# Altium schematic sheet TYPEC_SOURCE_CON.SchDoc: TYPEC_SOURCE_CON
size A4; SheetNumber: 5; SheetTotal: 10
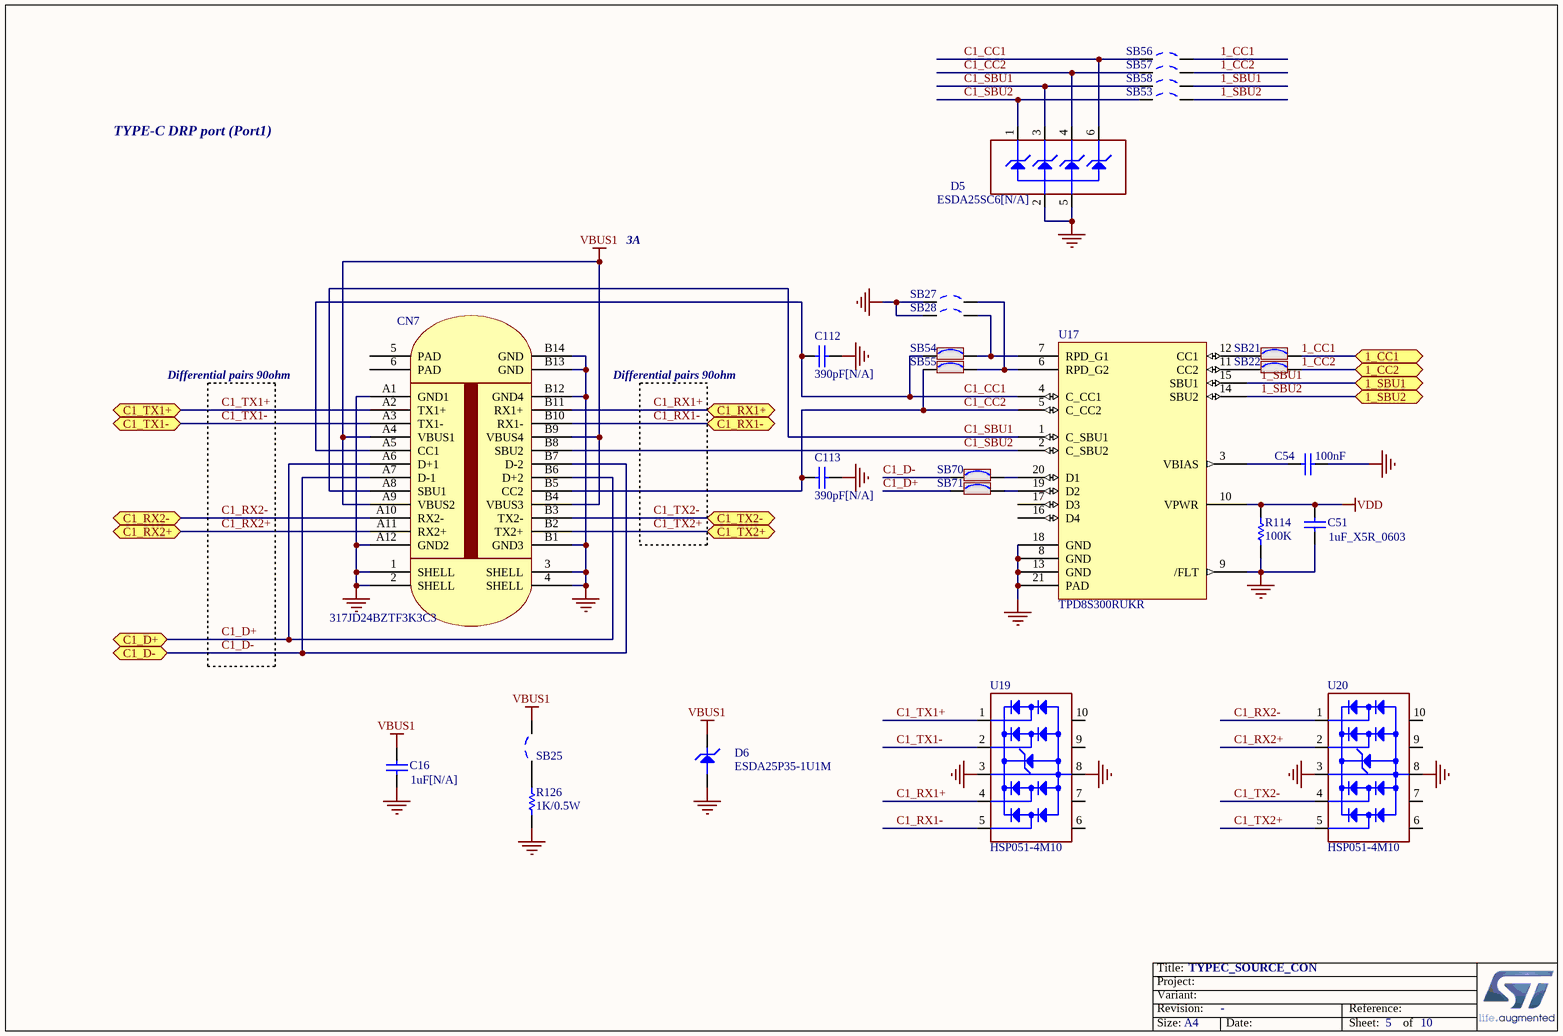
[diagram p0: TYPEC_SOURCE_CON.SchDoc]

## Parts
C16  1uF[N/A]  [0603C]
C51  1uF_X5R_0603  [0603C]
C54  100nF  [0603C]
C112  390pF[N/A]  [0603C]
C113  390pF[N/A]  [0603C]
CN7  317JD24BZTF3K3C3  [USB_C_632723300011]
D5  ESDA25SC6[N/A]  [SOT23-6L]
D6  ESDA25P35-1U1M  [D0603_21]
R114  100K  [0603R]
R126  1K/0.5W  [1210R]
SB21  Solder Bridge ON  [SB_0603]  (value not drawn)
SB22  Solder Bridge ON  [SB_0603]  (value not drawn)
SB25  Solder Bridge OFF  [SB_0603]  (value not drawn)
SB27  Solder Bridge OFF  [SB_0603]  (value not drawn)
SB28  Solder Bridge OFF  [SB_0603]  (value not drawn)
SB53  Solder Bridge OFF  [SB_0603]  (value not drawn)
SB54  Solder Bridge ON  [SB_0603]  (value not drawn)
SB55  Solder Bridge ON  [SB_0603]  (value not drawn)
SB56  Solder Bridge OFF  [SB_0603]  (value not drawn)
SB57  Solder Bridge OFF  [SB_0603]  (value not drawn)
SB58  Solder Bridge OFF  [SB_0603]  (value not drawn)
SB70  Solder Bridge ON  [SB_0603]  (value not drawn)
SB71  Solder Bridge ON  [SB_0603]  (value not drawn)
U17  TPD8S300RUKR  [QFN20_0R4_3X3_TP1R75]
U19  HSP051-4M10  [DFN10_0R5_2R5X1]
U20  HSP051-4M10  [DFN10_0R5_2R5X1]

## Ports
1_CC1 (bidir), 1_CC2 (bidir), 1_SBU1 (bidir), 1_SBU2 (bidir), C1_D+ (bidir), C1_D- (bidir), C1_RX1+ (bidir), C1_RX1- (bidir), C1_RX2+ (bidir), C1_RX2- (bidir), C1_TX1+ (bidir), C1_TX1- (bidir), C1_TX2+ (bidir), C1_TX2- (bidir)

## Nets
GND: C16.1 C51.1 C54.2 C112.1 C113.1 CN7.1(SHELL) CN7.2(SHELL) CN7.3(SHELL) CN7.4(SHELL) CN7.A1(GND1) CN7.A12(GND2) CN7.B1(GND3) CN7.B12(GND4) CN7.B13(GND) CN7.B14(GND) D5.2(GND) D5.5(IO4) D6.2 R114.2 R126.2 SB27.1 SB28.1 U17.8(GND) U17.9(/FLT) U17.13(GND) U17.18(GND) U17.21(PAD) U19.3(GND) U19.8(GND) U20.3(GND) U20.8(GND)
VBUS1: C16.2 CN7.A4(VBUS1) CN7.A9(VBUS2) CN7.B4(VBUS3) CN7.B9(VBUS4) D6.1 SB25.2
VDD: C51.2 R114.1 U17.10(VPWR)
1_CC1: SB21.2 SB56.2 ; port 1_CC1
1_CC2: SB22.2 SB57.2 ; port 1_CC2
1_SBU1: SB58.2 U17.15(SBU1) ; port 1_SBU1
1_SBU2: SB53.2 U17.14(SBU2) ; port 1_SBU2
C1_CC1: C112.2 CN7.A5(CC1) D5.6(IO5) SB54.1 SB56.1 U17.4(C_CC1)
C1_CC2: C113.2 CN7.B5(CC2) D5.4(IO3) SB55.1 SB57.1 U17.5(C_CC2)
C1_D+: CN7.A6(D+1) CN7.B6(D+2) SB71.1 ; port C1_D+
C1_D-: CN7.A7(D-1) CN7.B7(D-2) SB70.1 ; port C1_D-
C1_RX1+: CN7.B11(RX1+) U19.4(IO3) ; port C1_RX1+
C1_RX1-: CN7.B10(RX1-) U19.5(IO4) ; port C1_RX1-
C1_RX2+: CN7.A11(RX2+) U20.2(IO2) ; port C1_RX2+
C1_RX2-: CN7.A10(RX2-) U20.1(IO1) ; port C1_RX2-
C1_SBU1: CN7.A8(SBU1) D5.3(IO2) SB58.1 U17.1(C_SBU1)
C1_SBU2: CN7.B8(SBU2) D5.1(IO1) SB53.1 U17.2(C_SBU2)
C1_TX1+: CN7.A2(TX1+) U19.1(IO1) ; port C1_TX1+
C1_TX1-: CN7.A3(TX1-) U19.2(IO2) ; port C1_TX1-
C1_TX2+: CN7.B2(TX2+) U20.5(IO4) ; port C1_TX2+
C1_TX2-: CN7.B3(TX2-) U20.4(IO3) ; port C1_TX2-
NetC54_1: C54.1 U17.3(VBIAS)
NetR126_1: R126.1 SB25.1
NetSB21_1: SB21.1 U17.12(CC1)
NetSB22_1: SB22.1 U17.11(CC2)
NetSB27_2: SB27.2 SB55.2 U17.6(RPD_G2)
NetSB28_2: SB28.2 SB54.2 U17.7(RPD_G1)
NetSB70_2: SB70.2 U17.20(D1)
NetSB71_2: SB71.2 U17.19(D2)

Not connected (* = marked no-connect by the designer): CN7 5(PAD) 6(PAD); U17 16(D4) 17(D3); U19 6(NC) 7(NC) 9(NC) 10(NC); U20 6(NC) 7(NC) 9(NC) 10(NC)

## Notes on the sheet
- TYPE-C DRP port (Port1)
- 3A
- Differential pairs 90ohm

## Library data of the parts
C16 C51 C112 C113 = CAP SMD 0603  X5R 1µF 25V 10%: 0603  X5R 1µF; Rated voltage: 25V; Tolerance: 10%
C54 = Cap: Capacitor; Value: 10nF
CN7 = USB TYPE-C
D5 = ESDA25SC6: 4-line ESD protection; Manuf_1: STM; Provided: ST; ECCN_US/EU: EAR99/NEC
D6 = ESDALC6V1-1U2
R114 R126 = res1: Resistor; Value: 1K
SB21 SB22 SB54 SB55 SB70 SB71 = SB_ON: Fitted: YES; Ordered by: Subcon
SB25 SB27 SB28 SB53 SB56-SB58 = SB_OFF: Fitted: NO; Ordered by: Subcon
U19 U20 = HSP051-4M10: 4-line ESD protection for high speed lines; Manuf_1: STM; Manuf_Part_1: ESDA5V3L; Ref St: 9179034; Provided: ST; ECCN_US/EU: EAR99/NEC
